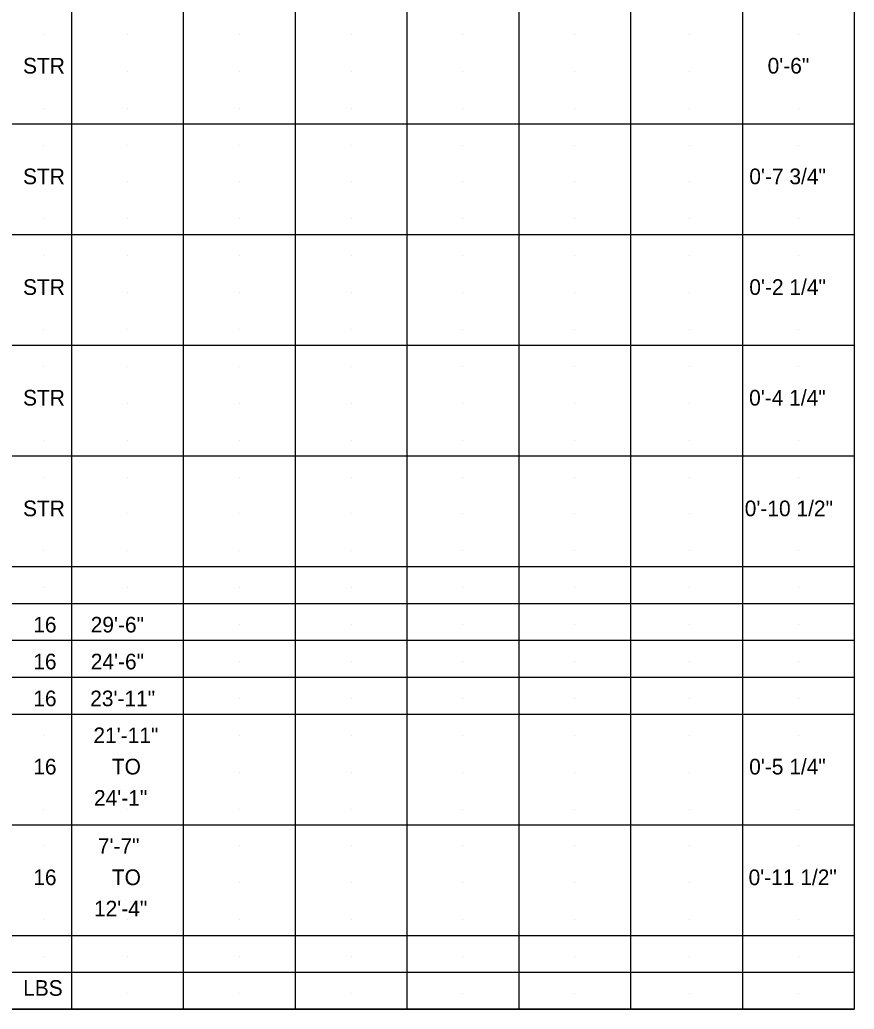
# Model space of a CAD drawing. Extents: x 2.9 to 17.4, y 3.2 to 21.1.
# Drawn here: x 9.91 to 17.37, y 3.22 to 12.07 of the extents above; entities that cross this region are included whole.
import ezdxf

# ---------------------------------------------------------------- set-up
doc = ezdxf.new("R2010")
doc.units = 0
doc.layers.add('BR_P_Gen_Text', color=7, linetype='Continuous')
doc.layers.add('SC_Scratch1', color=7, linetype='Continuous')

msp = doc.modelspace()

# ---------------------------------------------------------------- linework, layer by layer
at = {"layer": 'BR_P_Gen_Text'}
for p, q in [((17.3686, 21.0518), (17.3686, 3.2219)), ((10.3686, 20.0019), (10.3686, 3.2219)), ((11.3686, 20.0019), (11.3686, 3.2219)), ((12.3686, 20.0019), (12.3686, 3.2219)), ((13.3686, 20.0019), (13.3686, 3.2219)), ((14.3686, 20.0019), (14.3686, 3.2219)), ((15.3686, 20.0019), (15.3686, 3.2219)), ((16.3686, 20.0019), (16.3686, 3.2219)), ((2.8685, 11.1419), (17.3686, 11.1419)), ((2.8685, 10.1519), (17.3686, 10.1519)), ((2.8685, 9.1619), (17.3686, 9.1619)), ((2.8685, 8.1719), (17.3686, 8.1719)), ((2.8685, 7.1819), (17.3686, 7.1819)), ((2.8685, 6.8519), (17.3686, 6.8519)), ((2.8685, 6.5219), (17.3686, 6.5219)), ((2.8685, 6.1919), (17.3686, 6.1919)), ((2.8685, 5.8619), (17.3686, 5.8619)), ((2.8685, 5.8619), (17.3686, 5.8619)), ((2.8685, 4.8719), (17.3686, 4.8719)), ((2.8685, 3.8819), (17.3686, 3.8819)), ((2.8685, 3.5519), (17.3686, 3.5519)), ((2.8685, 3.5519), (17.3686, 3.5519)), ((17.3686, 3.2219), (2.8685, 3.2219)), ((2.8685, 3.2219), (17.3686, 3.2219)), ((2.8685, 3.2219), (17.3686, 3.2219))]:
    msp.add_line(p, q, dxfattribs=at)
at = {"layer": 'SC_Scratch1'}
for p, q in [((10.1186, 11.9419), (10.1186, 11.9419)), ((10.1186, 11.9419), (10.1186, 11.9419)), ((10.8686, 11.9419), (10.8686, 11.9419)), ((10.8686, 11.9419), (10.8686, 11.9419)), ((11.8692, 11.9419), (11.8692, 11.9419)), ((11.8692, 11.9419), (11.8692, 11.9419)), ((12.8686, 11.9419), (12.8686, 11.9419)), ((12.8686, 11.9419), (12.8686, 11.9419)), ((13.8686, 11.9419), (13.8686, 11.9419)), ((14.8686, 11.9419), (14.8686, 11.9419)), ((15.8914, 11.9419), (15.8914, 11.9419)), ((16.8686, 11.9419), (16.8686, 11.9419)), ((10.1186, 11.6119), (10.1186, 11.6119)), ((10.1186, 11.6119), (10.1186, 11.6119)), ((10.8686, 11.6119), (10.8686, 11.6119)), ((10.8686, 11.6119), (10.8686, 11.6119)), ((11.8692, 11.6119), (11.8692, 11.6119)), ((11.8692, 11.6119), (11.8692, 11.6119)), ((12.8686, 11.6119), (12.8686, 11.6119)), ((12.8686, 11.6119), (12.8686, 11.6119)), ((13.8686, 11.6119), (13.8686, 11.6119)), ((14.8686, 11.6119), (14.8686, 11.6119)), ((15.8914, 11.6119), (15.8914, 11.6119)), ((16.8686, 11.6119), (16.8686, 11.6119)), ((10.1186, 11.2819), (10.1186, 11.2819)), ((10.1186, 11.2819), (10.1186, 11.2819)), ((10.8686, 11.2819), (10.8686, 11.2819)), ((10.8686, 11.2819), (10.8686, 11.2819)), ((11.8692, 11.2819), (11.8692, 11.2819)), ((11.8692, 11.2819), (11.8692, 11.2819)), ((12.8686, 11.2819), (12.8686, 11.2819)), ((12.8686, 11.2819), (12.8686, 11.2819)), ((13.8686, 11.2819), (13.8686, 11.2819)), ((14.8686, 11.2819), (14.8686, 11.2819)), ((15.8914, 11.2819), (15.8914, 11.2819)), ((16.8686, 11.2819), (16.8686, 11.2819)), ((10.1186, 10.9519), (10.1186, 10.9519)), ((10.1186, 10.9519), (10.1186, 10.9519)), ((10.8686, 10.9519), (10.8686, 10.9519)), ((10.8686, 10.9519), (10.8686, 10.9519)), ((11.8692, 10.9519), (11.8692, 10.9519)), ((11.8692, 10.9519), (11.8692, 10.9519)), ((12.8686, 10.9519), (12.8686, 10.9519)), ((12.8686, 10.9519), (12.8686, 10.9519)), ((13.8686, 10.9519), (13.8686, 10.9519)), ((14.8686, 10.9519), (14.8686, 10.9519)), ((15.8914, 10.9519), (15.8914, 10.9519)), ((16.8686, 10.9519), (16.8686, 10.9519)), ((10.1186, 10.6219), (10.1186, 10.6219)), ((10.1186, 10.6219), (10.1186, 10.6219)), ((10.8686, 10.6219), (10.8686, 10.6219)), ((10.8686, 10.6219), (10.8686, 10.6219)), ((11.8692, 10.6219), (11.8692, 10.6219)), ((11.8692, 10.6219), (11.8692, 10.6219)), ((12.8686, 10.6219), (12.8686, 10.6219)), ((12.8686, 10.6219), (12.8686, 10.6219)), ((13.8686, 10.6219), (13.8686, 10.6219)), ((14.8686, 10.6219), (14.8686, 10.6219)), ((15.8914, 10.6219), (15.8914, 10.6219)), ((16.8686, 10.6219), (16.8686, 10.6219)), ((10.1186, 10.2919), (10.1186, 10.2919)), ((10.1186, 10.2919), (10.1186, 10.2919)), ((10.8686, 10.2919), (10.8686, 10.2919)), ((10.8686, 10.2919), (10.8686, 10.2919)), ((11.8692, 10.2919), (11.8692, 10.2919)), ((11.8692, 10.2919), (11.8692, 10.2919)), ((12.8686, 10.2919), (12.8686, 10.2919)), ((12.8686, 10.2919), (12.8686, 10.2919)), ((13.8686, 10.2919), (13.8686, 10.2919)), ((14.8686, 10.2919), (14.8686, 10.2919)), ((15.8914, 10.2919), (15.8914, 10.2919)), ((16.8686, 10.2919), (16.8686, 10.2919)), ((10.1186, 9.9619), (10.1186, 9.9619)), ((10.1186, 9.9619), (10.1186, 9.9619)), ((10.8686, 9.9619), (10.8686, 9.9619)), ((10.8686, 9.9619), (10.8686, 9.9619)), ((11.8692, 9.9619), (11.8692, 9.9619)), ((11.8692, 9.9619), (11.8692, 9.9619)), ((12.8686, 9.9619), (12.8686, 9.9619)), ((12.8686, 9.9619), (12.8686, 9.9619)), ((13.8686, 9.9619), (13.8686, 9.9619)), ((14.8686, 9.9619), (14.8686, 9.9619)), ((15.8914, 9.9619), (15.8914, 9.9619)), ((16.8686, 9.9619), (16.8686, 9.9619)), ((10.1186, 9.6319), (10.1186, 9.6319)), ((10.1186, 9.6319), (10.1186, 9.6319)), ((10.8686, 9.6319), (10.8686, 9.6319)), ((10.8686, 9.6319), (10.8686, 9.6319)), ((11.8692, 9.6319), (11.8692, 9.6319)), ((11.8692, 9.6319), (11.8692, 9.6319)), ((12.8686, 9.6319), (12.8686, 9.6319)), ((12.8686, 9.6319), (12.8686, 9.6319)), ((13.8686, 9.6319), (13.8686, 9.6319)), ((14.8686, 9.6319), (14.8686, 9.6319)), ((15.8914, 9.6319), (15.8914, 9.6319)), ((16.8686, 9.6319), (16.8686, 9.6319)), ((10.1186, 9.3019), (10.1186, 9.3019)), ((10.1186, 9.3019), (10.1186, 9.3019)), ((10.8686, 9.3019), (10.8686, 9.3019)), ((10.8686, 9.3019), (10.8686, 9.3019)), ((11.8692, 9.3019), (11.8692, 9.3019)), ((11.8692, 9.3019), (11.8692, 9.3019)), ((12.8686, 9.3019), (12.8686, 9.3019)), ((12.8686, 9.3019), (12.8686, 9.3019)), ((13.8686, 9.3019), (13.8686, 9.3019)), ((14.8686, 9.3019), (14.8686, 9.3019)), ((15.8914, 9.3019), (15.8914, 9.3019)), ((16.8686, 9.3019), (16.8686, 9.3019)), ((10.1186, 8.9719), (10.1186, 8.9719)), ((10.1186, 8.9719), (10.1186, 8.9719)), ((10.8686, 8.9719), (10.8686, 8.9719)), ((10.8686, 8.9719), (10.8686, 8.9719)), ((11.8692, 8.9719), (11.8692, 8.9719)), ((11.8692, 8.9719), (11.8692, 8.9719)), ((12.8686, 8.9719), (12.8686, 8.9719)), ((12.8686, 8.9719), (12.8686, 8.9719)), ((13.8686, 8.9719), (13.8686, 8.9719)), ((14.8686, 8.9719), (14.8686, 8.9719)), ((15.8914, 8.9719), (15.8914, 8.9719)), ((16.8686, 8.9719), (16.8686, 8.9719)), ((10.1186, 8.6419), (10.1186, 8.6419)), ((10.1186, 8.6419), (10.1186, 8.6419)), ((10.8686, 8.6419), (10.8686, 8.6419)), ((10.8686, 8.6419), (10.8686, 8.6419)), ((11.8692, 8.6419), (11.8692, 8.6419)), ((11.8692, 8.6419), (11.8692, 8.6419)), ((12.8686, 8.6419), (12.8686, 8.6419)), ((12.8686, 8.6419), (12.8686, 8.6419)), ((13.8686, 8.6419), (13.8686, 8.6419)), ((14.8686, 8.6419), (14.8686, 8.6419)), ((15.8914, 8.6419), (15.8914, 8.6419)), ((16.8686, 8.6419), (16.8686, 8.6419)), ((10.1186, 8.3119), (10.1186, 8.3119)), ((10.1186, 8.3119), (10.1186, 8.3119)), ((10.8686, 8.3119), (10.8686, 8.3119)), ((10.8686, 8.3119), (10.8686, 8.3119)), ((11.8692, 8.3119), (11.8692, 8.3119)), ((11.8692, 8.3119), (11.8692, 8.3119)), ((12.8686, 8.3119), (12.8686, 8.3119)), ((12.8686, 8.3119), (12.8686, 8.3119)), ((13.8686, 8.3119), (13.8686, 8.3119)), ((14.8686, 8.3119), (14.8686, 8.3119)), ((15.8914, 8.3119), (15.8914, 8.3119)), ((16.8686, 8.3119), (16.8686, 8.3119)), ((10.1186, 7.9819), (10.1186, 7.9819)), ((10.1186, 7.9819), (10.1186, 7.9819)), ((10.8686, 7.9819), (10.8686, 7.9819)), ((10.8686, 7.9819), (10.8686, 7.9819)), ((11.8692, 7.9819), (11.8692, 7.9819)), ((11.8692, 7.9819), (11.8692, 7.9819)), ((12.8686, 7.9819), (12.8686, 7.9819)), ((12.8686, 7.9819), (12.8686, 7.9819)), ((13.8686, 7.9819), (13.8686, 7.9819)), ((14.8686, 7.9819), (14.8686, 7.9819)), ((15.8914, 7.9819), (15.8914, 7.9819)), ((16.8686, 7.9819), (16.8686, 7.9819)), ((10.1186, 7.6519), (10.1186, 7.6519)), ((10.1186, 7.6519), (10.1186, 7.6519)), ((10.8686, 7.6519), (10.8686, 7.6519)), ((10.8686, 7.6519), (10.8686, 7.6519)), ((11.8692, 7.6519), (11.8692, 7.6519)), ((11.8692, 7.6519), (11.8692, 7.6519)), ((12.8686, 7.6519), (12.8686, 7.6519)), ((12.8686, 7.6519), (12.8686, 7.6519)), ((13.8686, 7.6519), (13.8686, 7.6519)), ((14.8686, 7.6519), (14.8686, 7.6519)), ((15.8914, 7.6519), (15.8914, 7.6519)), ((16.8686, 7.6519), (16.8686, 7.6519)), ((10.1186, 7.3219), (10.1186, 7.3219)), ((10.1186, 7.3219), (10.1186, 7.3219)), ((10.8686, 7.3219), (10.8686, 7.3219)), ((10.8686, 7.3219), (10.8686, 7.3219)), ((11.8692, 7.3219), (11.8692, 7.3219)), ((11.8692, 7.3219), (11.8692, 7.3219)), ((12.8686, 7.3219), (12.8686, 7.3219)), ((12.8686, 7.3219), (12.8686, 7.3219)), ((13.8686, 7.3219), (13.8686, 7.3219)), ((14.8686, 7.3219), (14.8686, 7.3219)), ((15.8914, 7.3219), (15.8914, 7.3219)), ((16.8686, 7.3219), (16.8686, 7.3219)), ((10.1186, 6.9919), (10.1186, 6.9919)), ((10.1186, 6.9919), (10.1186, 6.9919)), ((10.8686, 6.9919), (10.8686, 6.9919)), ((10.8686, 6.9919), (10.8686, 6.9919)), ((11.8692, 6.9919), (11.8692, 6.9919)), ((11.8692, 6.9919), (11.8692, 6.9919)), ((12.8686, 6.9919), (12.8686, 6.9919)), ((12.8686, 6.9919), (12.8686, 6.9919)), ((13.8686, 6.9919), (13.8686, 6.9919)), ((14.8686, 6.9919), (14.8686, 6.9919)), ((15.8914, 6.9919), (15.8914, 6.9919)), ((16.8686, 6.9919), (16.8686, 6.9919)), ((10.1186, 6.6619), (10.1186, 6.6619)), ((10.1186, 6.6619), (10.1186, 6.6619)), ((10.8686, 6.6619), (10.8686, 6.6619)), ((10.8686, 6.6619), (10.8686, 6.6619)), ((11.8692, 6.6619), (11.8692, 6.6619)), ((11.8692, 6.6619), (11.8692, 6.6619)), ((12.8686, 6.6619), (12.8686, 6.6619)), ((12.8686, 6.6619), (12.8686, 6.6619)), ((13.8686, 6.6619), (13.8686, 6.6619)), ((14.8686, 6.6619), (14.8686, 6.6619)), ((15.8914, 6.6619), (15.8914, 6.6619)), ((16.8686, 6.6619), (16.8686, 6.6619)), ((10.1186, 6.3319), (10.1186, 6.3319)), ((10.1186, 6.3319), (10.1186, 6.3319)), ((10.8686, 6.3319), (10.8686, 6.3319)), ((10.8686, 6.3319), (10.8686, 6.3319)), ((11.8692, 6.3319), (11.8692, 6.3319)), ((11.8692, 6.3319), (11.8692, 6.3319)), ((12.8686, 6.3319), (12.8686, 6.3319)), ((12.8686, 6.3319), (12.8686, 6.3319)), ((13.8686, 6.3319), (13.8686, 6.3319)), ((14.8686, 6.3319), (14.8686, 6.3319)), ((15.8914, 6.3319), (15.8914, 6.3319)), ((16.8686, 6.3319), (16.8686, 6.3319)), ((10.1186, 6.0019), (10.1186, 6.0019)), ((10.1186, 6.0019), (10.1186, 6.0019)), ((10.8686, 6.0019), (10.8686, 6.0019)), ((10.8686, 6.0019), (10.8686, 6.0019)), ((11.8692, 6.0019), (11.8692, 6.0019)), ((11.8692, 6.0019), (11.8692, 6.0019)), ((12.8686, 6.0019), (12.8686, 6.0019)), ((12.8686, 6.0019), (12.8686, 6.0019)), ((13.8686, 6.0019), (13.8686, 6.0019)), ((14.8686, 6.0019), (14.8686, 6.0019)), ((15.8914, 6.0019), (15.8914, 6.0019)), ((16.8686, 6.0019), (16.8686, 6.0019)), ((10.1186, 5.6719), (10.1186, 5.6719)), ((10.1186, 5.6719), (10.1186, 5.6719)), ((10.8686, 5.6719), (10.8686, 5.6719)), ((10.8686, 5.6719), (10.8686, 5.6719)), ((11.8692, 5.6719), (11.8692, 5.6719)), ((11.8692, 5.6719), (11.8692, 5.6719)), ((12.8686, 5.6719), (12.8686, 5.6719)), ((12.8686, 5.6719), (12.8686, 5.6719)), ((13.8686, 5.6719), (13.8686, 5.6719)), ((14.8686, 5.6719), (14.8686, 5.6719)), ((15.8914, 5.6719), (15.8914, 5.6719)), ((16.8686, 5.6719), (16.8686, 5.6719)), ((10.1186, 5.3419), (10.1186, 5.3419)), ((10.1186, 5.3419), (10.1186, 5.3419)), ((10.8686, 5.3419), (10.8686, 5.3419)), ((10.8686, 5.3419), (10.8686, 5.3419)), ((11.8692, 5.3419), (11.8692, 5.3419)), ((11.8692, 5.3419), (11.8692, 5.3419)), ((12.8686, 5.3419), (12.8686, 5.3419)), ((12.8686, 5.3419), (12.8686, 5.3419)), ((13.8686, 5.3419), (13.8686, 5.3419)), ((14.8686, 5.3419), (14.8686, 5.3419)), ((15.8914, 5.3419), (15.8914, 5.3419)), ((16.8686, 5.3419), (16.8686, 5.3419)), ((10.1186, 5.0119), (10.1186, 5.0119)), ((10.1186, 5.0119), (10.1186, 5.0119)), ((10.8686, 5.0119), (10.8686, 5.0119)), ((10.8686, 5.0119), (10.8686, 5.0119)), ((11.8692, 5.0119), (11.8692, 5.0119)), ((11.8692, 5.0119), (11.8692, 5.0119)), ((12.8686, 5.0119), (12.8686, 5.0119)), ((12.8686, 5.0119), (12.8686, 5.0119)), ((13.8686, 5.0119), (13.8686, 5.0119)), ((14.8686, 5.0119), (14.8686, 5.0119)), ((15.8914, 5.0119), (15.8914, 5.0119)), ((16.8686, 5.0119), (16.8686, 5.0119)), ((10.1186, 4.6819), (10.1186, 4.6819)), ((10.1186, 4.6819), (10.1186, 4.6819)), ((10.8686, 4.6819), (10.8686, 4.6819)), ((10.8686, 4.6819), (10.8686, 4.6819)), ((11.8692, 4.6819), (11.8692, 4.6819)), ((11.8692, 4.6819), (11.8692, 4.6819)), ((12.8686, 4.6819), (12.8686, 4.6819)), ((12.8686, 4.6819), (12.8686, 4.6819)), ((13.8686, 4.6819), (13.8686, 4.6819)), ((14.8686, 4.6819), (14.8686, 4.6819)), ((15.8914, 4.6819), (15.8914, 4.6819)), ((16.8686, 4.6819), (16.8686, 4.6819)), ((10.1186, 4.3519), (10.1186, 4.3519)), ((10.1186, 4.3519), (10.1186, 4.3519)), ((10.8686, 4.3519), (10.8686, 4.3519)), ((10.8686, 4.3519), (10.8686, 4.3519)), ((11.8692, 4.3519), (11.8692, 4.3519)), ((11.8692, 4.3519), (11.8692, 4.3519)), ((12.8686, 4.3519), (12.8686, 4.3519)), ((12.8686, 4.3519), (12.8686, 4.3519)), ((13.8686, 4.3519), (13.8686, 4.3519)), ((14.8686, 4.3519), (14.8686, 4.3519)), ((15.8914, 4.3519), (15.8914, 4.3519)), ((16.8686, 4.3519), (16.8686, 4.3519)), ((10.1186, 4.0219), (10.1186, 4.0219)), ((10.1186, 4.0219), (10.1186, 4.0219)), ((10.8686, 4.0219), (10.8686, 4.0219)), ((10.8686, 4.0219), (10.8686, 4.0219)), ((11.8692, 4.0219), (11.8692, 4.0219)), ((11.8692, 4.0219), (11.8692, 4.0219)), ((12.8686, 4.0219), (12.8686, 4.0219)), ((12.8686, 4.0219), (12.8686, 4.0219)), ((13.8686, 4.0219), (13.8686, 4.0219)), ((14.8686, 4.0219), (14.8686, 4.0219)), ((15.8914, 4.0219), (15.8914, 4.0219)), ((16.8686, 4.0219), (16.8686, 4.0219)), ((10.1186, 3.6919), (10.1186, 3.6919)), ((10.1186, 3.6919), (10.1186, 3.6919)), ((10.8686, 3.6919), (10.8686, 3.6919)), ((10.8686, 3.6919), (10.8686, 3.6919)), ((11.8692, 3.6919), (11.8692, 3.6919)), ((11.8692, 3.6919), (11.8692, 3.6919)), ((12.8686, 3.6919), (12.8686, 3.6919)), ((12.8686, 3.6919), (12.8686, 3.6919)), ((13.8686, 3.6919), (13.8686, 3.6919)), ((14.8686, 3.6919), (14.8686, 3.6919)), ((15.8914, 3.6919), (15.8914, 3.6919)), ((16.8686, 3.6919), (16.8686, 3.6919)), ((10.1186, 3.3619), (10.1186, 3.3619)), ((10.1186, 3.3619), (10.1186, 3.3619)), ((10.8686, 3.3619), (10.8686, 3.3619)), ((10.8686, 3.3619), (10.8686, 3.3619)), ((11.8692, 3.3619), (11.8692, 3.3619)), ((11.8692, 3.3619), (11.8692, 3.3619)), ((12.8686, 3.3619), (12.8686, 3.3619)), ((12.8686, 3.3619), (12.8686, 3.3619)), ((13.8686, 3.3619), (13.8686, 3.3619)), ((14.8686, 3.3619), (14.8686, 3.3619)), ((15.8914, 3.3619), (15.8914, 3.3619)), ((16.8686, 3.3619), (16.8686, 3.3619))]:
    msp.add_line(p, q, dxfattribs=at)

# ---------------------------------------------------------------- texts
at = {"layer": 'BR_P_Gen_Text'}
for s, p in [('STR', (9.9351, 11.5919)), ('0\'-6"', (16.5942, 11.5919)), ('STR', (9.9351, 10.6019)), ('0\'-7 3/4"', (16.4305, 10.6019)), ('STR', (9.9351, 9.6119)), ('0\'-2 1/4"', (16.4305, 9.6119)), ('STR', (9.9351, 8.6219)), ('0\'-4 1/4"', (16.4288, 8.6219)), ('STR', (9.9351, 7.6319)), ('0\'-10 1/2"', (16.3897, 7.6319)), ('16', (10.0266, 6.5919)), ('29\'-6"', (10.5402, 6.5919)), ('16', (10.0266, 6.2619)), ('24\'-6"', (10.5407, 6.2619)), ('16', (10.0266, 5.9319)), ('23\'-11"', (10.5358, 5.9319)), ('21\'-11"', (10.5645, 5.6019)), ('16', (10.0266, 5.3219)), ('TO', (10.7292, 5.3219)), ('0\'-5 1/4"', (16.4294, 5.3219)), ('24\'-1"', (10.5694, 5.0419)), ('7\'-7"', (10.6041, 4.6119)), ('16', (10.0266, 4.3319)), ('TO', (10.7292, 4.3319)), ('0\'-11 1/2"', (16.424, 4.3319)), ('12\'-4"', (10.5694, 4.0519)), ('LBS', (9.9362, 3.3419))]:
    msp.add_text(s, height=0.14, dxfattribs=at).set_placement(p)

doc.saveas('drawing.dxf')
